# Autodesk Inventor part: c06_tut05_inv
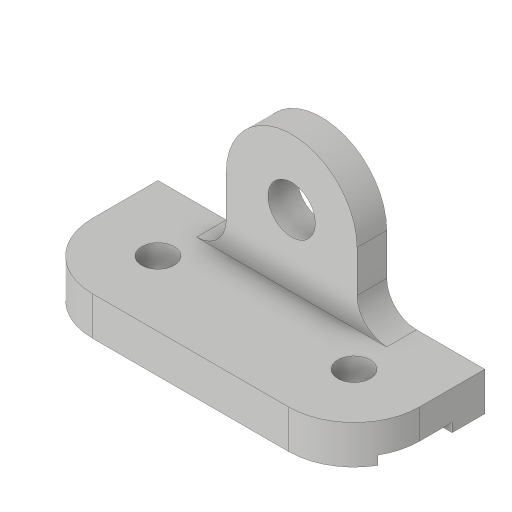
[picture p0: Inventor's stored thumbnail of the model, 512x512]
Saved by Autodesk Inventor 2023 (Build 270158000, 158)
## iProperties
Created: 2015-03
Part Number: c06_tut05_inv
Material: Generic
Document SubType Name: Modeling
Designer: Sandeep
Density: 1 g/cm^3
Appearance: Default
Author: Sandeep
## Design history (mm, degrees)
sketch "Sketch1"
  geometry: L1 (-11, 0)-(11, 0); L2 (11, 0)-(11, -3); L3 (11, -3)-(22, -3); L4 (22, -3)-(22, 10); L5 (22, 10)-(-22, 10); L6 (-22, 10)-(-22, -3); L7 (-22, -3)-(-11, -3); L8 (-11, -3)-(-11, 0); L9 (0, 13.216)-(0, -4.005); 2 further points
  constraints: 18 end point, 6 perpendicular, 4 point on line, 2 midpoint, 1 horizontal, 1 vertical, 1 other
  dimensions: "d0" = 22 distance of L1.start L1.end; "d1" = 44 distance of L4.end L5.end; "d2" = 3 distance between parallel lines of L1 L3; "d3" = 13 distance between parallel lines of L5 L3
extrude "Extrusion1" new body sketch "Sketch1" stored distance "d4" = 110; taper "d5" = 0 deg
fillet "Fillet1" dims "d6" = 22
mirror "Mirror1"
sketch "Sketch2"
  geometry: L1 (22, 0)-(88, 0) reference; L2 (77, 0)-(77, -24); L3 (33, -24)-(33, 0); L4 (77, 0)-(33, 0); L5 (0, 13)-(110, 13) reference; L6 (0, 0)-(0, 13) reference; C1 r 8 at (55, -24); A1 r 22 centre (55, -24) between (33, -24) and (77, -24); 1 further point
  constraints: 6 end point, 2 centre point, 2 point on circle, 2 point on line, 2 tangent, 1 coincident, 1 collinear, 1 parallel, 1 vertical
  dimensions: "d7" = 22 radius of A1; "d8" = 37 distance from line of L5 A1.centre; "d9" = 55 distance from line of L6 A1.centre; "d23" = 16 diameter of C1
extrude "Extrusion2" join sketch "Sketch2" distance "d11" = 10; taper "d12" = 0 deg
fillet "Fillet2" dims "d13" = 10
mirror "Mirror2"
hole "Hole1" diameter "d16" = 11; stored, may be unused: countersink angle "d20" = 90 deg, drill point angle "d22" = 118 deg; dims "d14" = 10, "d15" = 10, "d17" = 6, "d18" = 4, "d19" = 2, "d21" = 8
mirror "Mirror3"
body "Solid1"
